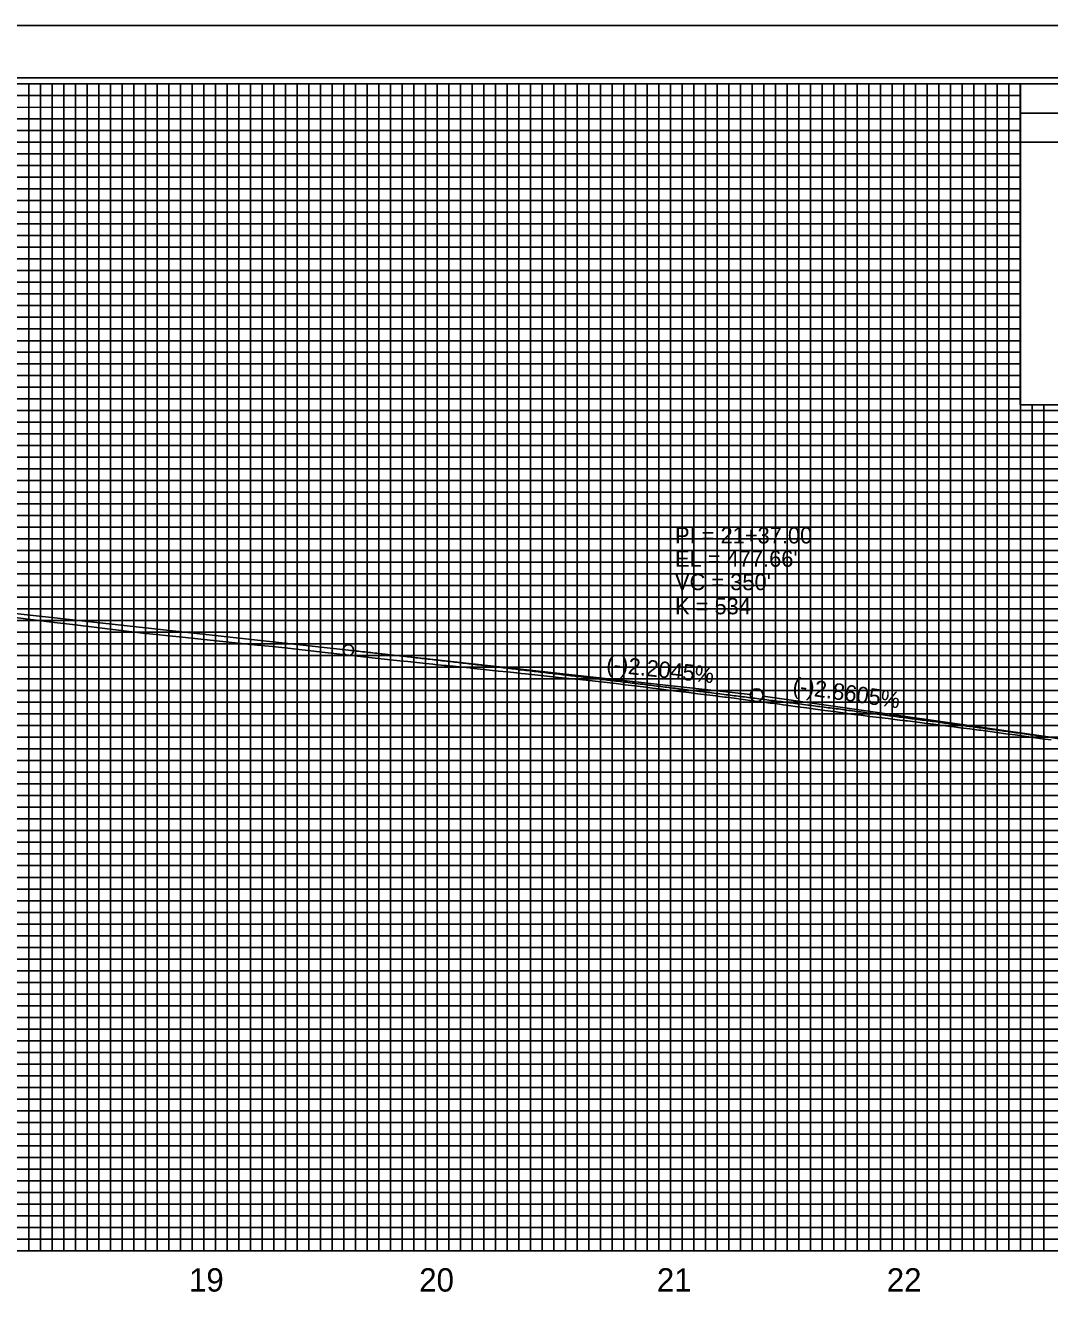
# Model space of a CAD drawing. Extents: x 571503 to 593215, y -77195 to -51828.
# Drawn here: x 582546 to 582985, y -53130 to -52584 of the extents above; entities that cross this region are included whole.
import ezdxf

# ---------------------------------------------------------------- set-up
doc = ezdxf.new("R2010")
doc.units = 0
for name, color, linetype in [('Exist Vertical Profile Ground Line', 7, 'Continuous'), ('Exist Vertical Profile Horizontal Axis Label Major', 7, 'Continuous'), ('Prop Vertical Profile Curve Label', 7, 'Continuous'), ('Prop Vertical Profile Grade', 7, 'Continuous'), ('Prop Vertical Profile Grade Label', 7, 'Continuous'), ('Prop VPI Label', 7, 'Continuous'), ('Sheet Clip Boundary CELL', 7, 'Continuous'), ('Sheet DOT Grid CELL', 7, 'Continuous'), ('Sheet Plot Border Inside CELL', 7, 'Continuous'), ('Sheet Plot Border Outside CELL', 7, 'Continuous'), ('Sheet Profile CELL', 7, 'Continuous'), ('Sheet Profile Grid Major CELL', 7, 'Continuous'), ('Sheet Profile Grid Middle CELL', 7, 'Continuous'), ('Sheet Profile Grid Minor CELL', 7, 'Continuous')]:
    doc.layers.add(name, color=color, linetype=linetype)

msp = doc.modelspace()

# ---------------------------------------------------------------- linework, layer by layer
at = {"layer": 'Exist Vertical Profile Ground Line'}
for points in [[(582541.64, -52837.32), (582558.63, -52839.49), (582566.33, -52840.33), (582590.52, -52843.41), (582596.37, -52844.04), (582613.42, -52845.85), (582621.34, -52846.64), (582645.41, -52849.18), (582652.05, -52849.79), (582658.62, -52850.45), (582674.53, -52852.32), (582697.22, -52854.97), (582706.61, -52855.91), (582709.98, -52856.26), (582713.86, -52856.67), (582717.74, -52857.07), (582720.77, -52857.39), (582721.63, -52857.47), (582725.51, -52857.86), (582726.61, -52857.98), (582729.4, -52858.26), (582733.28, -52858.65), (582736.71, -52859), (582737.17, -52859.05), (582741.05, -52859.46), (582744.93, -52859.88), (582748.82, -52860.29), (582752.7, -52860.71), (582756.59, -52861.13), (582758.57, -52861.35), (582760.47, -52861.55), (582764.36, -52861.99), (582768.24, -52862.42), (582772.12, -52862.85), (582773.26, -52862.98), (582776.01, -52863.24), (582778.95, -52863.52), (582779.89, -52863.61), (582783.78, -52863.98), (582787.66, -52864.36), (582787.71, -52864.36), (582791.55, -52864.8), (582795.43, -52865.25)], [(582795.43, -52865.25), (582799.31, -52865.7), (582803.2, -52866.15), (582807.08, -52866.61), (582810.9, -52867.06), (582810.97, -52867.07), (582814.85, -52867.6), (582817.63, -52867.99), (582818.74, -52868.12), (582822.62, -52868.59), (582826.5, -52869.06), (582830.39, -52869.54), (582834.27, -52870.01), (582838.16, -52870.49), (582842.04, -52870.97), (582842.46, -52871.02), (582844.68, -52871.3), (582845.93, -52871.46), (582846.49, -52871.54), (582849.81, -52871.97), (582853.69, -52872.49), (582857.58, -52873), (582861.46, -52873.52), (582865.35, -52874.03), (582866.14, -52874.14), (582869.23, -52874.55), (582870.8, -52874.77), (582873.12, -52875.08), (582877, -52875.6), (582880.88, -52876.12), (582884.77, -52876.65), (582888.65, -52877.17), (582892.54, -52877.7), (582896.42, -52878.23), (582899.4, -52878.64), (582900.02, -52878.72), (582900.31, -52878.76), (582902.32, -52879.01), (582904.19, -52879.24), (582908.07, -52879.72), (582911.96, -52880.2), (582915.84, -52880.68), (582919.73, -52881.16), (582923.32, -52881.61), (582923.61, -52881.64), (582924.12, -52881.71), (582927.5, -52882.13), (582931.38, -52882.61), (582935.26, -52883.1), (582939.15, -52883.59), (582943.03, -52884.09), (582946.92, -52884.58), (582950.8, -52885.07), (582954.69, -52885.57), (582954.79, -52885.58), (582955.62, -52885.69), (582958.57, -52886.09), (582962.45, -52886.62), (582966.34, -52887.15), (582970.22, -52887.68), (582974.11, -52888.21), (582976.08, -52888.49), (582976.85, -52888.61), (582977.99, -52888.76), (582981.88, -52889.3), (582985.76, -52889.84)]]:
    msp.add_lwpolyline(points, dxfattribs=at)
at = {"layer": 'Prop Vertical Profile Curve Label'}
msp.add_circle((582684.51, -52851.36), 2.25, dxfattribs=at)
at = {"layer": 'Prop Vertical Profile Grade'}
msp.add_line((582532.51, -52834.61), (582684.51, -52851.36), dxfattribs=at)
msp.add_spline([(582684.51, -52851.36), (582691.51, -52852.13), (582698.51, -52852.91), (582705.51, -52853.7), (582712.51, -52854.48), (582719.51, -52855.28), (582726.51, -52856.07), (582733.51, -52856.87), (582740.51, -52857.68), (582747.51, -52858.49), (582754.51, -52859.31), (582761.51, -52860.13), (582768.51, -52860.95), (582775.51, -52861.78), (582782.51, -52862.61), (582789.51, -52863.45), (582796.51, -52864.29), (582803.51, -52865.14), (582810.51, -52865.99), (582817.51, -52866.85), (582824.51, -52867.71), (582831.51, -52868.58), (582838.51, -52869.45), (582845.51, -52870.32), (582852.51, -52871.2), (582859.51, -52872.08), (582866.51, -52872.97), (582873.51, -52873.87), (582880.51, -52874.76), (582887.51, -52875.67), (582894.51, -52876.57), (582901.51, -52877.49), (582908.51, -52878.4), (582915.51, -52879.32), (582922.51, -52880.25), (582929.51, -52881.18), (582936.51, -52882.11), (582943.51, -52883.05), (582950.51, -52884), (582957.51, -52884.94), (582964.51, -52885.9), (582971.51, -52886.85), (582978.51, -52887.82), (582985.51, -52888.78), (582992.51, -52889.75), (582999.51, -52890.73), (583006.51, -52891.71), (583013.51, -52892.7), (583020.51, -52893.69), (583027.51, -52894.68), (583034.51, -52895.68)], degree=3, dxfattribs=at)
at = {"layer": 'Prop VPI Label'}
for p, q in [((582684.51, -52851.36), (582856.78, -52870.35)), ((583034.51, -52895.68), (582862.23, -52871.04))]:
    msp.add_line(p, q, dxfattribs=at)
msp.add_circle((582859.51, -52870.65), 2.75, dxfattribs=at)
at = {"layer": 'Sheet Clip Boundary CELL'}
msp.add_lwpolyline([(581722.51, -52608.7), (581722.51, -53108.7), (583122.51, -53108.7), (583122.51, -52746.25), (582972.46, -52746.25), (582972.46, -52608.7)], close=True, dxfattribs=at)
at = {"layer": 'Sheet DOT Grid CELL'}
for p, q in [((582572.51, -53108.7), (582572.51, -52608.7)), ((582572.51, -53108.7), (582572.51, -52608.7)), ((582622.51, -53108.7), (582622.51, -52608.7)), ((582622.51, -53108.7), (582622.51, -52608.7)), ((582672.51, -53108.7), (582672.51, -52608.7)), ((582672.51, -53108.7), (582672.51, -52608.7)), ((582722.51, -53108.7), (582722.51, -52608.7)), ((582722.51, -53108.7), (582722.51, -52608.7)), ((582772.51, -53108.7), (582772.51, -52608.7)), ((582772.51, -53108.7), (582772.51, -52608.7)), ((582822.51, -53108.7), (582822.51, -52608.7)), ((582822.51, -53108.7), (582822.51, -52608.7)), ((582872.51, -53108.7), (582872.51, -52608.7)), ((582872.51, -53108.7), (582872.51, -52608.7)), ((582922.51, -53108.7), (582922.51, -52608.7)), ((582922.51, -53108.7), (582922.51, -52608.7)), ((581672.51, -52658.7), (582972.46, -52658.7)), ((582972.46, -52658.7), (581672.51, -52658.7)), ((581672.51, -52708.7), (582972.46, -52708.7)), ((582972.46, -52708.7), (581672.51, -52708.7)), ((582972.51, -53108.7), (582972.51, -52746.25)), ((582972.51, -53108.7), (582972.51, -52746.25)), ((581672.51, -52758.7), (583172.51, -52758.7)), ((583172.51, -52758.7), (581672.51, -52758.7)), ((581672.51, -52808.7), (583172.51, -52808.7)), ((583172.51, -52808.7), (581672.51, -52808.7)), ((581672.51, -52858.7), (583172.51, -52858.7)), ((583172.51, -52858.7), (581672.51, -52858.7)), ((581672.51, -52908.7), (583172.51, -52908.7)), ((583172.51, -52908.7), (581672.51, -52908.7)), ((581672.51, -52958.7), (583172.51, -52958.7)), ((583172.51, -52958.7), (581672.51, -52958.7)), ((581672.51, -53008.7), (583172.51, -53008.7)), ((583172.51, -53008.7), (581672.51, -53008.7)), ((581672.51, -53058.7), (583172.51, -53058.7)), ((583172.51, -53058.7), (581672.51, -53058.7))]:
    msp.add_line(p, q, dxfattribs=at)
at = {"layer": 'Sheet Plot Border Inside CELL'}
msp.add_lwpolyline([(581518.51, -53661.25), (583185.01, -53661.25), (583185.01, -52606.15), (581518.51, -52606.15)], close=True, dxfattribs=at)
at = {"layer": 'Sheet Plot Border Outside CELL'}
msp.add_lwpolyline([(581505.51, -53683.7), (583189.51, -53683.7), (583189.51, -52583.7), (581505.51, -52583.7)], close=True, dxfattribs=at)
at = {"layer": 'Sheet Profile CELL'}
for p, q in [((583189.51, -52583.7), (581505.51, -52583.7)), ((582972.46, -52621.25), (583172.51, -52621.25)), ((581672.51, -53108.7), (583172.51, -53108.7))]:
    msp.add_line(p, q, dxfattribs=at)
for points in [[(583172.51, -52608.7), (581672.51, -52608.7), (581672.51, -53658.7), (583172.51, -53658.7)], [(582972.46, -52608.7), (583172.51, -52608.7), (583172.51, -52633.75), (582972.46, -52633.75)], [(582972.46, -52633.75), (583072.51, -52633.75), (583072.51, -52746.25), (582972.46, -52746.25)]]:
    msp.add_lwpolyline(points, close=True, dxfattribs=at)
at = {"layer": 'Sheet Profile Grid Major CELL'}
for points in [[(582522.51, -53108.7), (582572.51, -53108.7), (582572.51, -52608.7), (582622.51, -52608.7), (582622.51, -53108.7), (582672.51, -53108.7), (582672.51, -52608.7), (582722.51, -52608.7), (582722.51, -53108.7), (582772.51, -53108.7), (582772.51, -52608.7), (582822.51, -52608.7), (582822.51, -53108.7), (582872.51, -53108.7), (582872.51, -52608.7), (582922.51, -52608.7), (582922.51, -53108.7), (582972.51, -53108.7), (582972.51, -52608.7), (582998.81, -52608.7)], [(581672.51, -52658.7), (582972.51, -52658.7)], [(582972.51, -52708.7), (581672.51, -52708.7), (581672.51, -52758.7), (583172.51, -52758.7)], [(583172.51, -52808.7), (581672.51, -52808.7), (581672.51, -52858.7), (583172.51, -52858.7)], [(583172.51, -52908.7), (581672.51, -52908.7), (581672.51, -52958.7), (583172.51, -52958.7)], [(583172.51, -53008.7), (581672.51, -53008.7), (581672.51, -53008.7), (581672.51, -53058.7), (583172.51, -53058.7)]]:
    msp.add_lwpolyline(points, dxfattribs=at)
at = {"layer": 'Sheet Profile Grid Middle CELL'}
msp.add_line((581672.51, -52633.7), (582972.46, -52633.7), dxfattribs=at)
for points in [[(582497.51, -52608.7), (582547.51, -52608.7), (582547.51, -53108.7), (582597.51, -53108.7), (582597.51, -52608.7), (582647.51, -52608.7), (582647.51, -53108.7), (582697.51, -53108.7), (582697.51, -52608.7), (582747.51, -52608.7), (582747.51, -53108.7), (582797.51, -53108.7), (582797.51, -52608.7), (582847.51, -52608.7), (582847.51, -53108.7), (582897.51, -53108.7), (582897.51, -52608.7), (582947.51, -52608.7), (582947.51, -53108.7), (582997.51, -53108.7), (582997.51, -52746.25)], [(582972.51, -52683.7), (581672.51, -52683.7), (581672.51, -52733.7), (582972.51, -52733.7)], [(583172.51, -52783.7), (581672.51, -52783.7), (581672.51, -52833.7), (582997.51, -52833.7)], [(583172.51, -52883.7), (581672.51, -52883.7), (581672.51, -52933.7), (583172.51, -52933.7)], [(583172.51, -52983.7), (581672.51, -52983.7), (581672.51, -53033.7), (583172.51, -53033.7)], [(583172.51, -53083.7), (581672.51, -53083.7)]]:
    msp.add_lwpolyline(points, dxfattribs=at)
at = {"layer": 'Sheet Profile Grid Minor CELL'}
for p, q in [((581722.51, -52613.7), (582972.51, -52613.7)), ((582972.51, -52618.7), (581722.51, -52619.05)), ((581722.51, -52623.7), (582972.51, -52623.7)), ((582972.46, -52743.7), (581722.51, -52743.7)), ((583122.51, -52748.7), (581722.51, -52748.7)), ((583122.51, -52753.7), (581722.51, -52753.7)), ((581722.51, -52763.7), (583122.51, -52763.7)), ((583122.51, -52768.7), (581722.51, -52768.7)), ((581722.51, -52773.7), (583122.51, -52773.7)), ((583122.51, -52793.7), (581722.51, -52793.7)), ((581722.51, -52798.7), (583122.51, -52798.7)), ((583122.51, -52818.7), (581722.51, -52818.7)), ((581722.51, -52823.7), (583122.51, -52823.7)), ((583122.51, -52843.7), (581722.51, -52843.7)), ((581722.51, -52848.7), (583122.51, -52848.7)), ((583122.51, -52853.7), (581722.51, -52853.7)), ((581722.51, -52863.7), (583122.51, -52863.7)), ((583122.51, -52868.7), (581722.51, -52868.7)), ((581722.51, -52873.7), (583122.51, -52873.7)), ((583122.51, -52878.7), (581722.51, -52878.7)), ((581722.51, -52888.7), (583122.51, -52888.7)), ((583122.51, -52893.7), (581722.51, -52893.7)), ((581722.51, -52898.7), (583122.51, -52898.7)), ((583122.51, -52903.7), (581722.51, -52903.7)), ((581722.51, -52913.7), (583122.51, -52913.7)), ((583122.51, -52918.7), (581722.51, -52918.7)), ((581722.51, -52923.7), (583122.51, -52923.7)), ((583122.51, -52928.7), (581722.51, -52928.7)), ((581722.51, -52938.7), (583122.51, -52938.7)), ((583122.51, -52943.7), (581722.51, -52943.7)), ((581722.51, -52948.7), (583122.51, -52948.7)), ((583122.51, -52953.7), (581722.51, -52953.7)), ((581722.51, -52963.7), (583122.51, -52963.7)), ((583122.51, -52968.7), (581722.51, -52968.7)), ((581722.51, -52973.7), (583122.51, -52973.7)), ((583122.51, -52978.7), (581722.51, -52978.7)), ((581722.51, -52988.7), (583122.51, -52988.7)), ((583122.51, -52993.7), (581722.51, -52993.7)), ((583122.51, -52998.7), (581722.51, -52998.7)), ((583122.51, -53003.7), (581722.51, -53003.7)), ((581722.51, -53013.7), (583122.51, -53013.7)), ((583122.51, -53018.7), (581722.51, -53018.7)), ((581722.51, -53023.7), (583122.51, -53023.7)), ((583122.51, -53028.7), (581722.51, -53028.7)), ((581722.51, -53038.7), (583122.51, -53038.7)), ((583122.51, -53043.7), (581722.51, -53043.7)), ((581722.51, -53048.7), (583122.51, -53048.7)), ((583122.51, -53053.7), (581722.51, -53053.7)), ((581722.51, -53063.7), (583122.51, -53063.7)), ((583122.51, -53068.7), (581722.51, -53068.7)), ((581722.51, -53073.7), (583122.51, -53073.7)), ((583122.51, -53078.7), (581722.51, -53078.7)), ((581722.51, -53088.7), (583122.51, -53088.7)), ((583122.51, -53093.7), (581722.51, -53093.7)), ((581722.51, -53098.7), (583122.51, -53098.7))]:
    msp.add_line(p, q, dxfattribs=at)
for points in [[(582542.51, -52608.7), (582552.51, -52608.7), (582552.51, -53108.7), (582557.51, -53108.7)], [(582557.51, -53108.7), (582557.51, -52608.7), (582562.51, -52608.7), (582562.51, -53108.7), (582567.51, -53108.7), (582567.51, -52608.7), (582577.51, -52608.7), (582577.51, -53108.7), (582582.51, -53108.7), (582582.51, -52608.7), (582587.51, -52608.7), (582587.51, -53108.7), (582592.51, -53108.7), (582592.51, -52608.7), (582602.51, -52608.7), (582602.51, -53108.7), (582607.51, -53108.7), (582607.51, -52608.7), (582612.51, -52608.7), (582612.51, -53108.7), (582617.51, -53108.7), (582617.51, -52608.7), (582627.51, -52608.7), (582627.51, -53108.7), (582632.51, -53108.7), (582632.51, -52608.7), (582637.51, -52608.7), (582637.51, -53108.7), (582642.51, -53108.7), (582642.51, -52608.7), (582652.51, -52608.7), (582652.51, -53108.7), (582657.51, -53108.7), (582657.51, -52608.7), (582662.51, -52608.7), (582662.51, -53108.7), (582667.51, -53108.7), (582667.51, -52608.7), (582677.51, -52608.7), (582677.51, -53108.7), (582682.51, -53108.7), (582682.51, -52608.7), (582687.51, -52608.7), (582687.51, -53108.7), (582692.51, -53108.7), (582692.51, -52608.7), (582702.51, -52608.7), (582702.51, -53108.7), (582707.51, -53108.7), (582707.51, -52608.7), (582712.51, -52608.7), (582712.51, -53108.7), (582717.51, -53108.7), (582717.51, -52608.7), (582727.51, -52608.7), (582727.51, -53108.7), (582732.51, -53108.7), (582732.51, -52608.7), (582737.51, -52608.7), (582737.51, -53108.7), (582742.51, -53108.7), (582742.51, -52608.7), (582752.51, -52608.7), (582752.51, -53108.7), (582757.51, -53108.7), (582757.51, -52608.7), (582762.51, -52608.7), (582762.51, -53108.7), (582767.51, -53108.7), (582767.51, -52608.7), (582777.51, -52608.7), (582777.51, -53108.7), (582782.51, -53108.7), (582782.51, -52608.7), (582787.51, -52608.7), (582787.51, -53108.7), (582792.51, -53108.7), (582792.51, -52608.7), (582802.51, -52608.7), (582802.51, -53108.7), (582807.51, -53108.7), (582807.51, -52608.7), (582812.51, -52608.7), (582812.51, -53108.7), (582817.51, -53108.7), (582817.51, -52608.7), (582827.51, -52608.7), (582827.51, -53108.7), (582832.51, -53108.7), (582832.51, -52608.7), (582837.51, -52608.7), (582837.51, -53108.7), (582842.51, -53108.7), (582842.51, -52608.7), (582852.51, -52608.7), (582852.51, -53108.7), (582857.51, -53108.7), (582857.51, -52608.7), (582862.51, -52608.7), (582862.51, -53108.7)], [(582862.51, -53108.7), (582867.51, -53108.7), (582867.51, -52608.7), (582877.51, -52608.7), (582877.51, -53108.7), (582882.51, -53108.7), (582882.51, -52608.7), (582887.51, -52608.7), (582887.51, -53108.7), (582892.51, -53108.7), (582892.51, -52608.7), (582902.51, -52608.7), (582902.51, -53108.7), (582907.51, -53108.7), (582907.51, -52608.7), (582912.51, -52608.7), (582912.51, -53108.7), (582917.51, -53108.7), (582917.51, -52608.7), (582927.51, -52608.7), (582927.51, -53108.7), (582932.51, -53108.7), (582932.51, -52608.7), (582937.51, -52608.7), (582937.51, -53108.7), (582942.51, -53108.7), (582942.51, -52608.7), (582952.51, -52608.7), (582952.51, -53108.7), (582957.51, -53108.7), (582957.51, -52608.7), (582962.51, -52608.7), (582962.51, -53108.7), (582967.51, -53108.7), (582967.51, -52608.7), (582977.51, -52608.7)], [(582972.51, -52628.7), (581722.51, -52628.7), (581722.51, -52638.7), (582972.51, -52638.7)], [(582972.46, -52643.7), (581722.51, -52643.7), (581722.51, -52648.7), (582972.51, -52648.7)], [(582972.51, -52653.7), (581722.51, -52653.7), (581722.51, -52663.7), (582972.51, -52663.7)], [(582972.51, -52668.7), (581722.51, -52668.7), (581722.51, -52673.7), (582972.51, -52673.7)], [(582972.51, -52678.7), (581722.51, -52678.7), (581722.51, -52688.7), (582972.51, -52688.7)], [(582972.51, -52693.7), (581722.51, -52693.7), (581722.51, -52698.7), (582972.51, -52698.7)], [(582972.51, -52703.7), (581722.51, -52703.7), (581722.51, -52713.7), (582972.51, -52713.7)], [(582972.51, -52718.8), (581722.61, -52718.8), (581722.61, -52723.7), (582972.51, -52723.7)], [(582972.51, -52728.7), (581722.51, -52728.7), (581722.51, -52738.7), (582972.51, -52738.7)], [(582977.51, -52746.25), (582977.51, -53108.7), (582982.51, -53108.7), (582982.51, -52746.25)], [(583122.51, -52778.7), (581722.51, -52778.7), (581722.51, -52788.7), (583122.51, -52788.7)], [(583122.51, -52803.7), (581722.51, -52803.7), (581722.51, -52813.7), (583122.51, -52813.7)], [(583122.51, -52828.7), (581722.51, -52828.7), (581722.51, -52838.7), (583122.51, -52838.7)], [(583122.51, -53103.7), (581722.51, -53103.7)]]:
    msp.add_lwpolyline(points, dxfattribs=at)

# ---------------------------------------------------------------- texts
at = {"layer": 'Exist Vertical Profile Horizontal Axis Label Major'}
for s, p in [('19', (582616.22, -53126.2)), ('20', (582714.89, -53126.2)), ('21', (582816.73, -53126.2)), ('22', (582915.28, -53126.2))]:
    msp.add_text(s, height=10, dxfattribs=at).set_placement(p)
at = {"layer": 'Prop Vertical Profile Curve Label'}
for s, p in [("VC = 350'", (582824.51, -52825.65)), ('K = 534', (582824.51, -52836))]:
    msp.add_text(s, height=7, dxfattribs=at).set_placement(p)
at = {"layer": 'Prop Vertical Profile Grade Label'}
for s, rotation, p in [('(-)2.2045%', 353.7099, (582794.83, -52860.5)), ('(-)2.8605%', 351.8606, (582874.6, -52869.78))]:
    msp.add_text(s, height=7, rotation=rotation, dxfattribs=at).set_placement(p)
at = {"layer": 'Prop VPI Label'}
for s, p in [('PI = 21+37.00', (582824.51, -52805.65)), ("EL = 477.66'", (582824.51, -52815.65))]:
    msp.add_text(s, height=7, dxfattribs=at).set_placement(p)

doc.saveas('drawing.dxf')
